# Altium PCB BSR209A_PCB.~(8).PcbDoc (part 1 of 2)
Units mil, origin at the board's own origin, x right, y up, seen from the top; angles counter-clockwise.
Board outline 3820.03 x 2030.03 mil, 4 copper layers (Top Layer, MidLayer1, MidLayer2, Bottom Layer), stack 59.4 mil thick; 68 components, 18 nets, 122 pads, 73 vias.
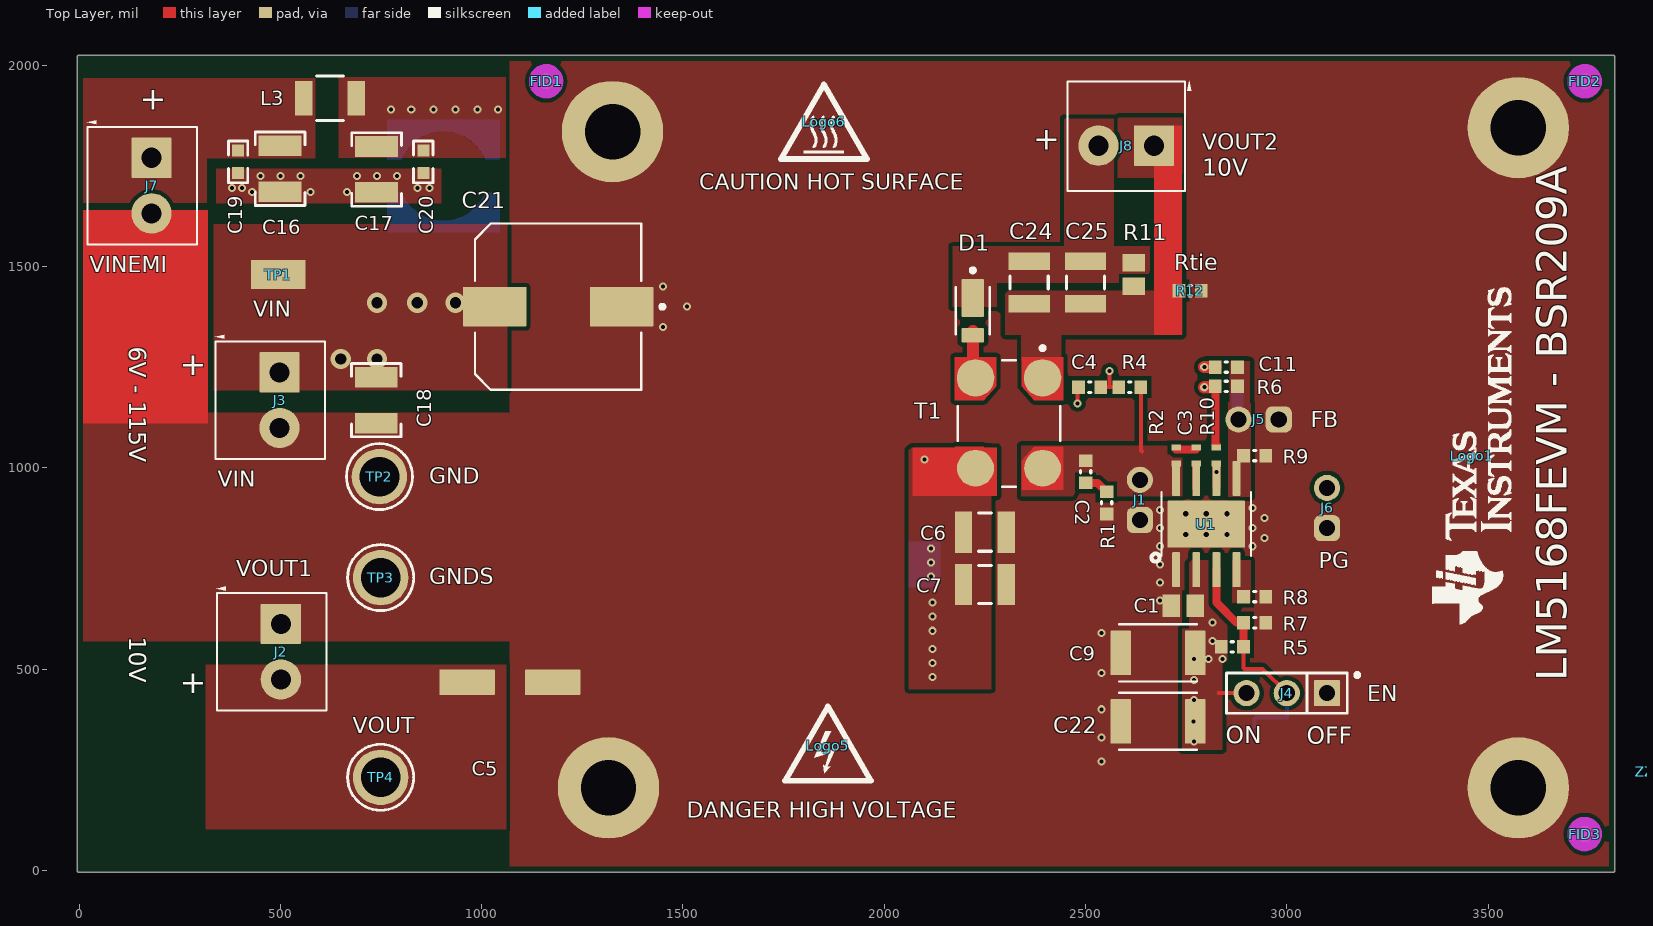
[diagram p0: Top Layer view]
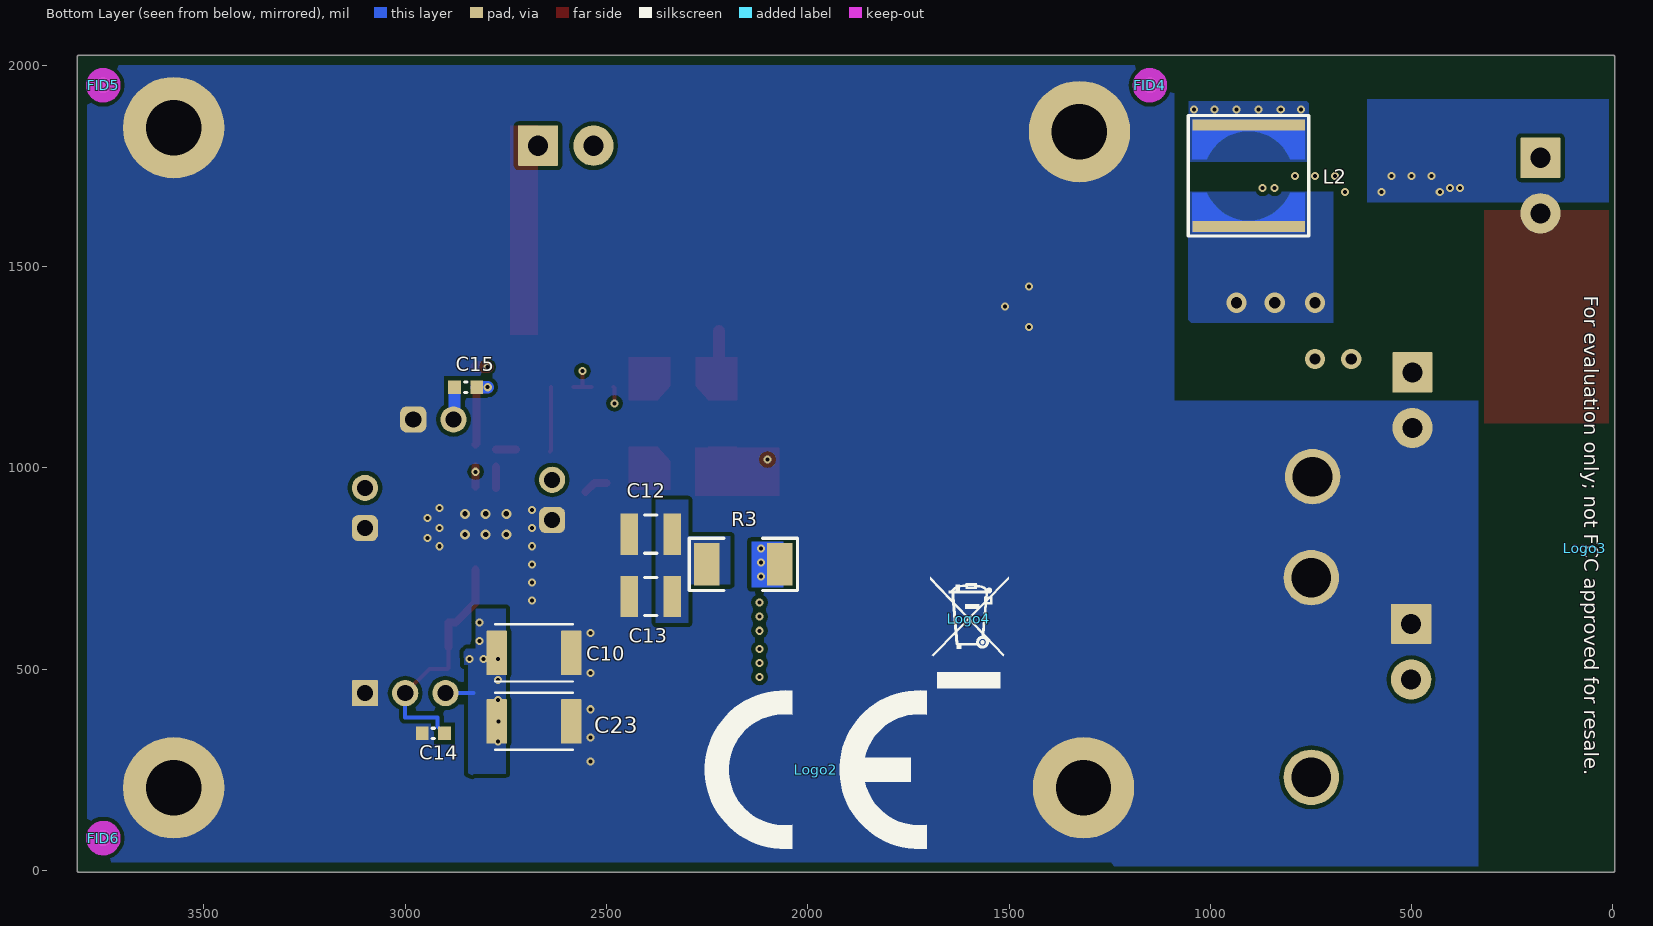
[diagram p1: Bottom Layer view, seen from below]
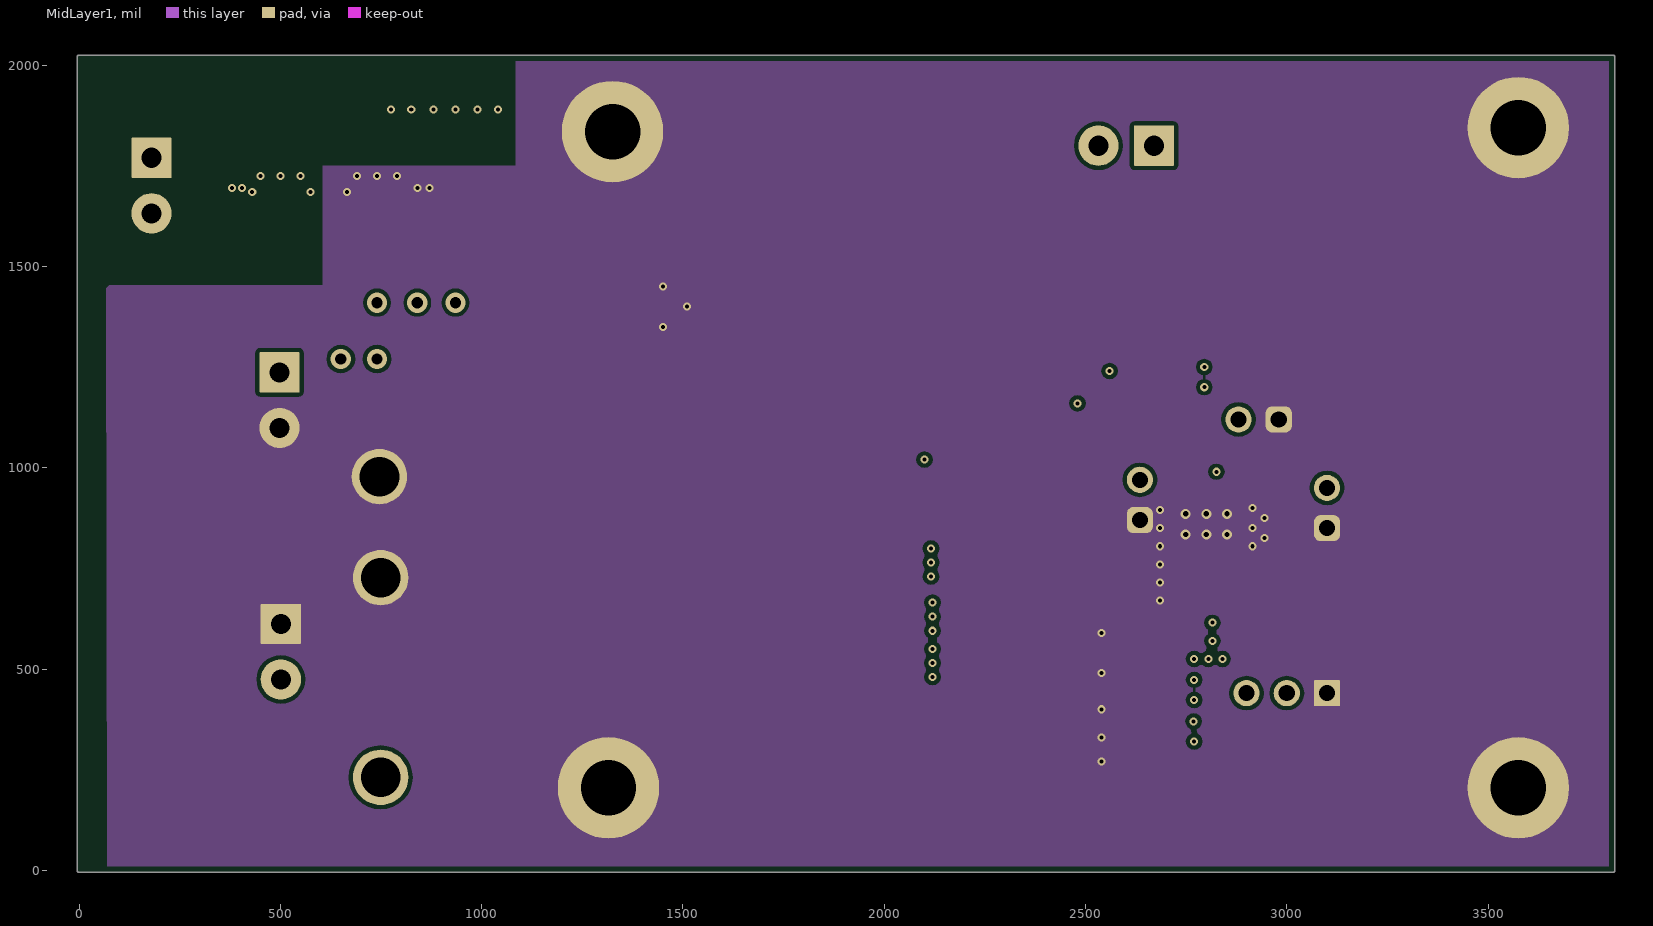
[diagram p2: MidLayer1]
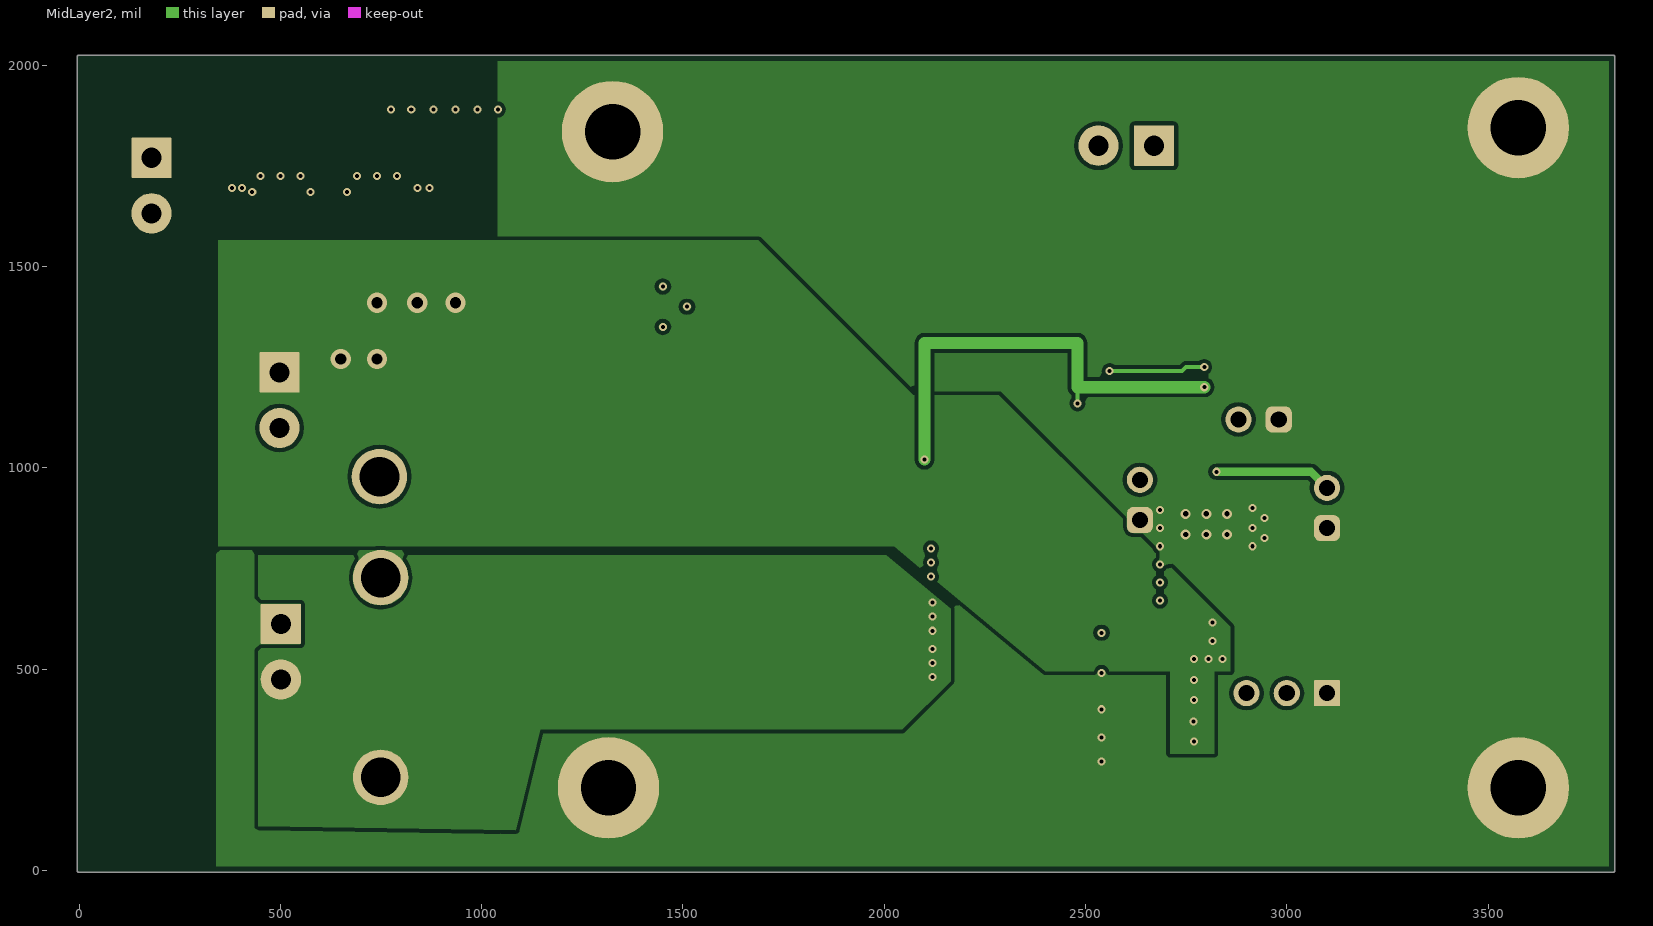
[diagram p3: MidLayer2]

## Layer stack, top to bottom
Top Solder: solder mask 0.4, Solder Resist, Dk 3.5
Top Layer: signal copper 2.8
Dielectric1: core 10, FR-4, Dk 4.8
MidLayer1: signal copper 1.4
Dielectric2: prepreg 31, FR-4, Dk 4.8
MidLayer2: signal copper 1.4
Dielectric3: core 10, FR-4, Dk 4.8
Bottom Layer: signal copper 2.8
Bottom Solder: solder mask 0.4, Solder Resist, Dk 3.5

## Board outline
0,-5.01 cw(c0,0) -5.02,0 -5.02,2020 cw(c0,2020) 0,2025.02 3810,2025.02 cw(c3810,2020) 3815.02,2020 3815.02,0 cw(c3810,0) 3810,-5.01 318,-5.01 cw(c318,0) 316.5,-4.79 cw(c315,0) 315,-5.01

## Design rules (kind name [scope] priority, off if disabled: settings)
AcuteAngle [All] p1: minimum=4.50000000000000E+0001 checktracksonly=TRUE
AssemblyTestPointUsage [All] p1: valid=2
BoardOutlineClearance BoardOutlineClearance_MountingHoles [OnCopper and InComponentClass('Mounting Holes')] p1: gap=40 ignorepadtopadclearanceinfootprint=FALSE
BoardOutlineClearance BoardOutlineClearance_Poly [OnCopper and IsPoly] p2: gap=15 ignorepadtopadclearanceinfootprint=FALSE
BoardOutlineClearance [OnCopper and Not InComponentClass('Logo') and not InComponentClass('FiducialMark') and not InRegion(1000,500,4000,800) and not InPoly] p3: gap=20 ignorepadtopadclearanceinfootprint=FALSE
Clearance Clearance_Keepouts [((IsTrack Or IsArc) And Not InPoly) And IsFree and IsKeepOut vs ((IsTrack Or IsArc) And Not InPoly) And IsFree and IsKeepOut] p1: gap=0 ignorepadtopadclearanceinfootprint=TRUE
Clearance Clearance_Poly [InPolygon] p2: gap=10 ignorepadtopadclearanceinfootprint=TRUE except(0: Arc-Hole Track-Hole SMDPad-Hole THPad-Hole Via-Hole Fill-Hole Poly-Hole Region-Hole Text-Hole)
Clearance Clearance_FiducialMark [IsKeepOut and InComponentClass('FiducialMark') vs IsPad and InComponentClass('FiducialMark')] p3: gap=0 ignorepadtopadclearanceinfootprint=TRUE
Clearance [All] p4: gap=5 ignorepadtopadclearanceinfootprint=TRUE except(0: Arc-Hole Track-Hole SMDPad-Hole THPad-Hole Via-Hole Fill-Hole Poly-Hole Region-Hole Text-Hole)
ComponentClearance ComponentClearance_MountingHoles_FiducialMarks [InComponentClass('Mounting Holes') vs InComponentClass('FiducialMark')] p1: gap=10 collisioncheckmode=3 verticalgap=10 showdistances=FALSE
ComponentClearance ComponentClearance_Shunt [InComponentClass('Header') vs InComponentClass('Shunt')] p2: gap=0 collisioncheckmode=3 verticalgap=0 showdistances=FALSE
ComponentClearance ComponentClearance_Logo [InComponentClass('Logo')] p3: gap=10 collisioncheckmode=3 verticalgap=10 showdistances=FALSE
ComponentClearance ComponentClearance_ScrewToNut [(HasFootprint('NY PMS 440 0025 PH')) vs (HasFootprint('Keystone_1902C'))] p4: gap=5 collisioncheckmode=3 verticalgap=10 showdistances=FALSE
ComponentClearance ComponentClearance_MountingHoles [InComponentClass('Mounting Holes')] p5: gap=10 collisioncheckmode=3 verticalgap=100000 showdistances=FALSE
ComponentClearance ComponentClearance_SmallPassives [HasFootprint('0201*') or HasFootprint('0402*') or HasFootprint('0508') or HasFootprint('0603*') or HasFootprint('0612') or HasFootprint('0805*') or HasFootprint('0815*') or HasFootprint('0830*') or HasFootprint('1206*') or HasFootprint('1210*') or HasFootprint('1808*') or HasFootprint('1812*') or HasFootprint('1825*') or HasFootprint('2010*') or HasFootprint('2220*') or HasFootprint('2225*') or HasFootprint('2512*') or HasFootprint('2728*') or HasFootprint('3518*') vs HasFootprint('0201*') or HasFootprint('0402*') or HasFootprint('0508') or HasFootprint('0603*') or HasFootprint('0612') or HasFootprint('0805*') or HasFootprint('0815*') or HasFootprint('0830*') or HasFootprint('1206*') or HasFootprint('1210*') or HasFootprint('1808*') or HasFootprint('1812*') or HasFootprint('1825*') or HasFootprint('2010*') or HasFootprint('2220*') or HasFootprint('2225*') or HasFootprint('2512*') or HasFootprint('2728*') or HasFootprint('3518*')] p6: gap=10 collisioncheckmode=3 verticalgap=10 showdistances=FALSE
ComponentClearance ComponentClearance_THtoSMT [IsThruComponent vs IsSMTComponent] p7: gap=10 collisioncheckmode=3 verticalgap=30 showdistances=FALSE
ComponentClearance ComponentClearance_THtoTH [IsThruComponent vs IsThruComponent] p8: gap=10 collisioncheckmode=3 verticalgap=30 showdistances=FALSE
ComponentClearance [All] p9: gap=10 collisioncheckmode=3 verticalgap=30 showdistances=FALSE
DiffPairsRouting [All] p1: maxlimit=100 minlimit=10 mostfreqgap=10 toplayer_minwidth=15 toplayer_maxwidth=15 toplayer_prefwidth=15 midlayer1_minwidth=15 midlayer1_maxwidth=15 midlayer1_prefwidth=15 midlayer2_minwidth=15 midlayer2_maxwidth=15 midlayer2_prefwidth=15 bottomlayer_minwidth=15 bottomlayer_maxwidth=15 bottomlayer_prefwidth=15 maxuncoupledlength=1000
FabricationTestPointUsage TestPointUsage [All] p1: valid=2 allowmultiple=FALSE
FabricationTestpoint Testpoint [All] p1: side=3 testpointundercomponent=TRUE minsize=40 maxsize=100 preferedsize=60 minholesize=0 maxholesize=40 preferedholesize=32 testpointgrid=1 allowsidetop=TRUE allowsidebottom=TRUE usegrid=TRUE gridtolerance=0.01
FanoutControl Fanout_LCC [IsLCC] p1: bgadir=Out bgaviamode=Centered fanoutstyle=Auto fanoutdirection=Alternating viagrid=1 // Fanout_LCC (Default Rule)
FanoutControl Fanout_BGA [IsBGA] p2: bgadir=Out bgaviamode=Centered fanoutstyle=Auto fanoutdirection=Alternating viagrid=1 // Fanout_BGA (Default Rule)
FanoutControl Fanout_Default [All] p4: bgadir=Out bgaviamode=Centered fanoutstyle=Auto fanoutdirection=Alternating viagrid=1 // Fanout_Default (Default Rule)
FanoutControl Fanout_Small [(CompPinCount < 5)] p5: bgadir=Out bgaviamode=Centered fanoutstyle=Auto fanoutdirection=OutThenIn viagrid=1 // Fanout_Small (Default Rule)
HoleSize [All] p1: absolutevalues=TRUE maxlimit=251 minlimit=7.87 maxpercent=80.000 minpercent=20.000
MinimumAnnularRing MinimumAnnularRing_ThermalPadVias [IsVia and InAnyComponent] p1: minimumring=5
MinimumAnnularRing [All] p2: minimumring=5
MinimumSolderMaskSliver MinimumSolderMaskSliver_Logo [InComponentClass('Logo') vs InComponentClass('Logo')] p1: minsoldermaskwidth=0.7
MinimumSolderMaskSliver [All] p2: minsoldermaskwidth=3.94
PlaneClearance PlaneClearance_1 [OnLayer('Top Layer')] p1: clearance=7.87
PlaneClearance [All] p2: clearance=9.84
PlaneConnect PlaneConnect_via [IsVia] p1: planeconnectstyle=Direct reliefexpansion=20 reliefentries=4 reliefconductorwidth=10 reliefairgap=10
PlaneConnect [All] p2: planeconnectstyle=Direct reliefexpansion=10 reliefentries=4 reliefconductorwidth=10 reliefairgap=10
PolygonConnect PolygonConnect_tp [(InComponent('TP*') or InComponent('J4*') or InComponent('J3*') or InComponent('X7') or InComponent('X9'))] p1: connectstyle=Direct reliefconductorwidth=10 reliefentries=4 polygonreliefangle="90 Angle" airgapwidth=10
PolygonConnect PolygonConnect_logo [InComponent('Logo1')] p2: connectstyle=Direct reliefconductorwidth=10 reliefentries=4 polygonreliefangle="90 Angle" airgapwidth=10
PolygonConnect PolygonConnect_Via [IsVia] p3: connectstyle=Direct reliefconductorwidth=10 reliefentries=4 polygonreliefangle="90 Angle" airgapwidth=10
PolygonConnect PolygonConnect_1 [HasFootprint('HARWIN_S1911-46R')] p4: connectstyle=Direct reliefconductorwidth=39.37 reliefentries=4 polygonreliefangle="90 Angle" airgapwidth=7.87
PolygonConnect PolygonConnect_poly [IsPoly] p5: connectstyle=Direct reliefconductorwidth=30 reliefentries=4 polygonreliefangle="90 Angle" airgapwidth=8
PolygonConnect [All] p6: connectstyle=Relief reliefconductorwidth=30 reliefentries=4 polygonreliefangle="90 Angle" airgapwidth=8
RoutingVias ThermalPadVias [IsVia and InAnyComponent] p1: holewidth=7.87 width=19.68 viastyle="Through Hole" minholewidth=7.87 minwidth=19.68 maxholewidth=12.99 maxwidth=25
RoutingVias [All] p2: holewidth=16 width=34 viastyle="Through Hole" minholewidth=7 minwidth=20 maxholewidth=40 maxwidth=65
SilkToSilkClearance SilkToSilkClearance_Pb-FreeLogo [(HasFootprint('Pb-Free_Overlay_Medium') OR HasFootprint('Pb-Free_Overlay_Small')) vs (HasFootprint('Pb-Free_Overlay_Medium') OR HasFootprint('Pb-Free_Overlay_Small'))] p1: silktosilkclearance=0
SilkToSilkClearance [All] p2: silktosilkclearance=3
SilkToSolderMaskClearance SilkToComponentPadClearance [(IsPad or IsFill or IsRegion) and InAnycomponent] p1: minsilkscreentomaskgap=5 clearancetoexposedcopper=TRUE
SilkToSolderMaskClearance "Silk to Solder Mask Opening" [All] p2: minsilkscreentomaskgap=4 clearancetoexposedcopper=FALSE
SolderMaskExpansion [All] p1: expansion=1.97
Width [All] p1: maxlimit=100 minlimit=6 preferedwidth=10 checkconnectedcopper=TRUE
15 further rules are at their usual default settings.

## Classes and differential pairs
component class FiducialMark: FID1 FID2 FID3 FID4 FID5 FID6
component class Header: J1 J4 J5 J6
component class Logo: Logo1
component class BSR209A_Hardware: !PCB FID1 FID2 FID3 FID4 FID5 FID6 Logo1 Logo2 Logo3 Logo4 Logo5 Logo6 ZZ2 ZZ3 ZZ4
component class AssemblyNote: ZZ2 ZZ3 ZZ4
component class BSR209A_sch: 30 500kHz C1 C2 C3 C4 C5 C6 C7 C9 C10 C11 C12 C13 C14 C15 C16 C17 C18 C19 C20 C21 C22 C23 C24 C25 CIN1 COUT2 COUT3 D1 gnd J1 J2 J3 J4 J5 J6 J7 J8 L2 L3 R1 R2 R3 R4 R5 R6 R7 R8 R9 R10 R11 R12 T1 TP1 TP2 TP3 TP4 TPCLK180 U1 vin Vout

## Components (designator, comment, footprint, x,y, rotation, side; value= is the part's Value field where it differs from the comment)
C1 "C2012X7T2E104K125AA" 0805L 2742.79,657.21 r180 top value=0.1uF
C2 "GRM188R72D102KW07D" 0603L 2500,990 r90 top value=1000pF
C3 "GCM155R71H222KA37D" 0402S 2775,1030 r270 top value=2200pF
C4 "CR" 0603L 2510,1200 r0 top value=3300pF
C5 "UWT1E101MCL1GS" UWT_630x770 1070,467 r0 top value=100uF
C6 "GRT32ER61E226KE13L" 1210_270L 2250,840 r0 top value=22uF
C7 "GRT32ER61E226KE13L" 1210_270L 2250,710 r0 top value=22uF
C9 "CGA8P3X7T2E105K250KE" FP-CGA8P3X7T2E105K250KE_1812-MFG 2680,540 r0 top value=1µF
C10 "CGA8P3X7T2E105K250KE" FP-CGA8P3X7T2E105K250KE_1812-MFG 2680,540 r0 bottom value=1µF
C11 "C0603C560J5GACTU" 0603L 2850,1250 r0 top value=56pF
C12 "COUT3" 1210_270L 2390,835 r0 bottom value=22uF
C13 "COUT4" 1210_270L 2390,680 r0 bottom value=22uF
C14 "CEN" 0603L 2930,340 r0 bottom value=0.01uF
C15 "CFF" 0603L 2850,1200 r0 bottom value=1000pF
C16 "CGA6M3X7S2A475K200AB" 1210_220 499,1743 r270 top value=4.7uF
C17 "CGA6M3X7S2A475K200AB" 1210_220 739,1741 r270 top value=4.7uF
C18 "CGA6M3X7S2A475K200AB" 1210_220 738,1168 r270 top value=4.7uF
C19 "HMK107B7104KAHT" 0603_HV 395,1760 r270 top value=0.1uF
C20 "HMK107B7104KAHT" 0603_HV 855,1760 r270 top value=0.1uF
C21 "ULT2C330MNL1GS" FP-ULT2C330MNL1GS_RADIAL-MFG 1190,1400 r180 top value=33µF
C22 "CGA8P3X7T2E105K250KE" FP-CGA8P3X7T2E105K250KE_1812-MFG 2680,370 r0 top value=1µF
C23 "CGA8P3X7T2E105K250KE" FP-CGA8P3X7T2E105K250KE_1812-MFG 2680,370 r0 bottom value=1µF
C24 "GRT32ER61E226KE13L" 1210_270L 2360,1460 r270 top value=22uF
C25 "GRT32ER61E226KE13L" 1210_270L 2500,1460 r270 top value=22uF
D1 "SS1H20LS RVG" "FP-SS1H20LS RVG_SOD123HE-MFG" 2220,1390 r270 top
FID1 "Fiducial" Fiducial10-20 1160,1960 r90 top
FID2 "Fiducial" Fiducial10-20 3740,1960 r90 top
FID3 "Fiducial" Fiducial10-20 3740,90 r90 top
FID4 "Fiducial" Fiducial10-20 1150,1950 r90 bottom
FID5 "Fiducial" Fiducial10-20 3750,1950 r90 bottom
FID6 "Fiducial" Fiducial10-20 3750,80 r90 bottom
J1 "SW" TSW-102-07-G-S 2635,920 r90 top
J2 "VOUT1" TERM_BLK_ED555-2DS 501,612 r270 top
J3 "VIN" TERM_BLK_ED555-2DS 498,1237 r270 top
J4 "EN" Samtec_HTSW-103-07-G-S 3000,440 r180 top
J5 "FB" TSW-102-07-G-S 2930,1120 r180 top
J6 "PG" TSW-102-07-G-S 3100,900 r90 top
J7 "VINEMI" TERM_BLK_ED555-2DS 180,1770 r270 top
J8 "VOUT2" TERM_BLK_ED555-2DS 2670,1800 r180 top
L2 "MSS7341T-153MLB" MSS7341 905,1725 r270 bottom value=15uH
L3 "FBMH3225HM202NT" 1210_280 623,1918 r0 top value="2000 ohm"
Logo1 "Texas Instruments" TI_Stacked_Overlay_Small 3460,1030 r90 top
Logo2 "CE Mark" CE_Mark_10mm 1980,250 r180 bottom
Logo3 "FCC disclaimer" FCC_disclaimer 70,800 r270 bottom
Logo4 "WEEE logo" WEEE_Minimum 1600,625 r180 bottom
Logo5 "DANGER HIGH VOLTAGE" IEC_HighVoltage_Small 1860,310 r0 top
Logo6 "CAUTION HOT SURFACE" IEC_HotSurface_Small 1850,1860 r0 top
R1 "CRCW06031R00JNEA" 0603L 2552.2,912.8 r90 top value=1.0
R2 "RBST" 0402S 2725,1030 r270 top value=0
R3 "DNP" 2010 2160,760 r180 bottom value=0.2
R4 "RC0603FR-07118KL" 0603L 2610,1200 r180 top value=118k
R5 "RC0603FR-071ML" 0603L 2865,555 r180 top value=1.00Meg
R6 "RC0603FR-07453KL" 0603L 2850,1202 r180 top value=453k
R7 "RC0603FR-07332KL" 0603L 2920,615 r180 top value=332k
R8 "RC0603FR-0733K2L" 0603L 2920,680 r180 top value=33.2k
R9 "RC0603FR-0761K9L" 0603L 2920,1030 r180 top value=61.9k
R10 "ERJ-2RKF1003X" 0402S 2825,1030 r90 top value=100k
R11 "CRCW08051K00FKEA" 0805L 2620,1480 r90 top value=1.00k
R12 "Rtie" 0603L 2760,1440 r0 top value=0
T1 "LPD8035V-333MRC" FP-LPD8035V-333MRC_SMD4-MFG 2310,1110 r270 top
TP1 "VIN" Harwin_S1751-46 495,1480 r0 top
TP2 "GND" Keystone1598-2 746,978 r90 top value=Triple
TP3 "GNDS" Keystone1598-2 749,727 r90 top value=Triple
TP4 "VOUT" Keystone1598-2 749,231 r90 top value=Triple
U1 "LM5168FQDDARQ1" DDA0008E-MFG 2800,860 r90 top
ZZ2 "These assemblies are ESD sensitive, ESD precautions shall be observed." AssemblyNote 4250,245 r90 top
ZZ3 "These assemblies must be clean and free from flux and all contaminants. Use of no clean flux is not acceptable." AssemblyNote 4070,245 r90 top
ZZ4 "These assemblies must comply with workmanship standards IPC-A-610 Class 2, unless otherwise specified." AssemblyNote 3900,245 r90 top

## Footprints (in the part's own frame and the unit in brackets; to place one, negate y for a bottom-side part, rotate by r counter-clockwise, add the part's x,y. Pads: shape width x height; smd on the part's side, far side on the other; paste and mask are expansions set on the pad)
0402S [mil] "Based on C0402S footprint from PADS legacy"
  rect 15x24 smd: 1(-20,0) 2(20,0)
  body extent -22,-12 22,12, height 24
0603_HV [mil] "Ernesto recommended land pattern.  26 mil between pads."
  rect 30x30 smd: 1(-28,0) 2(28,0)
  silkscreen extent -52,-24 52,24, body extent -34,-19 34,19, height 39
0603L [mm] "0603 from SM-752 data"
  rect 0.8x0.85 smd: 1(-0.7,0) 2(0.7,0)
  silkscreen extent -0.07,-0.33 0.07,0.33, body extent -0.87,-0.47 0.87,0.47, height 1
0805L [mm] "0805 from SM-752 data"
  rect 1.1x1.4 smd: 1(-0.75,0) 2(0.75,0)
  body extent -1.1,-0.72 1.1,0.72, height 1.45
1210_220 [mm] "1210"
  rect 1.3x2.7 smd: 1(-1.45,0) 2(1.45,0)
  silkscreen extent -2.32,-1.57 2.32,1.57, body extent -1.7,-1.35 1.7,1.35, height 2.2
1210_270L [mm] "1210"
  rect 1.1x2.6 smd: 1(-1.35,0) 2(1.35,0)
  silkscreen extent -0.4,-1.2 0.4,1.2, body extent -1.7,-1.35 1.7,1.35, height 2.7
1210_280 [mm] "SMD, 2-Leads, Body 3.6x2.8mm, Height 2.8mm"
  rect 1.1x2.2 smd: 1(-1.65,0) 2(1.65,0)
  silkscreen extent -0.84,-1.4 0.84,1.4, body extent -1.8,-1.4 1.8,1.4, height 2.8
2010 [mm] "Chip Capacitor, Body 5.08x2.54mm, IPC Medium Density"
  rect 1.6x2.7 smd: 1(-2.3,0) 2(2.3,0)
  silkscreen extent -3.42,-1.65 3.42,1.65, body extent -2.73,-1.45 2.73,1.45, height 1.66
AssemblyNote [mil] "Assembly Note"
CE_Mark_10mm [mil] "Double the minimum text height for CE Mark"
  silkscreen extent -275,-197 276,197
DDA0008E-MFG [mm]
  rrect20% 2.2x0.5 smd paste-1000 mask+0: 1(-2.875,1.905) 2(-2.875,0.635) 3(-2.875,-0.635) 4(-2.875,-1.905) 5(2.875,-1.905) 6(2.875,-0.635) 7(2.875,0.635) 8(2.875,1.905)
  rrect3% 2.95x4.9 smd paste-1000 mask-1000: 9(0,0)
  silkscreen extent -2,-2.83 2,2.83, body extent -4.08,-2.68 4.08,2.68, height 0.25
FCC_disclaimer [mil]
Fiducial10-20 [mm]
  round 1 smd mask+0.5: 1(0,0)
  Top Layer keep-out circle w1.178: c0,0 r0.5
FP-CGA8P3X7T2E105K250KE_1812-MFG [mm]
  rrect8% 1.3x2.8 smd paste+0 mask+0: 1(-2.35,0) 2(2.35,0)
  silkscreen extent -2.45,-1.8 2.45,1.8, body extent -3.1,-1.9 3.1,1.9, height 0.25
FP-LPD8035V-333MRC_SMD4-MFG [mm]
  round 2.367 smd paste+0 mask+0: 1(-2.875,2.115) 2(-2.875,-2.115)
  round 2.325 smd paste+0 mask+0: 3(2.822,-2.115) 4(2.822,2.115)
  Top Layer region: 4.19,-3.43 1.455,-3.43 1.455,-1.6 2.36,-0.8 4.19,-0.8
  Top Layer region: 4.19,3.43 1.455,3.43 1.455,1.6 2.36,0.8 4.19,0.8
  Top Layer region: -4.19,-3.43 -1.455,-3.43 -1.455,-1.6 -2.36,-0.8 -4.19,-0.8
  Top Layer region: -4.19,3.43 -1.455,3.43 -1.455,1.6 -2.36,0.8 -4.19,0.8
  silkscreen extent -4.87,-3.24 4,3.24, body extent -4.29,-3.53 4.29,3.53, height 0.25
"FP-SS1H20LS RVG_SOD123HE-MFG" [mm]
  rrect7% 2.4x1.4 smd paste+0 mask+0: 1(-0.8,0)
  rrect11% 0.9x1.4 smd paste+0 mask+0: 2(1.55,0)
  silkscreen extent -2.67,-1.07 1.5,1.07, body extent -2.1,-1.07 2.1,1.07, height 0.25
FP-ULT2C330MNL1GS_RADIAL-MFG [mm]
  rrect4% 4x2.5 smd paste+0 mask+0: 1(-4,0) 2(4,0)
  silkscreen extent -6.7,-5.25 5.25,5.25, body extent -6.25,-5.5 6.25,5.5, height 0.25
Harwin_S1751-46 [mm] "Test Point, Body 3.25x1.65mm"
  rect 3.45x1.85 smd: 1(0,0)
  body extent -1.62,-0.82 1.63,0.82, height 2.05
IEC_HighVoltage_Small [mil]
  silkscreen extent -107,-88 107,97
IEC_HotSurface_Small [mil]
  silkscreen extent -107,-93 107,92
Keystone1598-2 [mm] "Triple Turret"
  round 3.5 hole 2.5: 1(0,0)
  silkscreen extent -2.08,-2.08 2.08,2.08, body extent -1.6,-1.6 1.59,1.6, height 7.72
MSS7341 [mm] "Coilcraft recommended land pattern Document 383-2 1/3/11"
  rect 0.7x7.1 smd: 1(-3.2,0) 2(3.2,0)
  Top Layer region: 1.05,3.55 3.55,3.55 3.55,-3.55 1.05,-3.55 1.05,-2.623 2.135,-1.85 2.745,-0.666 2.745,0.666 2.135,1.85 1.05,2.623 1.05,2.623
  Top Layer region: -1.05,3.55 -3.55,3.55 -3.55,-3.55 -1.05,-3.55 -1.05,-2.623 -2.135,-1.85 -2.745,-0.666 -2.745,0.666 -2.135,1.85 -1.05,2.623 -1.05,2.623
  silkscreen extent -3.8,-3.8 3.8,3.8, body extent -3.78,-3.78 3.78,3.78, height 4.12
Samtec_HTSW-103-07-G-S [mm] "Samtec 100mil, 1x3, 230 mil above insulator"
  rrect6% 1.65x1.65 hole 1.016: 1(-2.54,0)
  round 1.65 hole 1.016: 2(0,0) 3(2.54,0)
  silkscreen extent -4.57,-1.27 3.81,1.27, body extent -3.81,-1.27 3.81,1.27, height 8.38
TERM_BLK_ED555-2DS [mil]
  rrect4% 100x100 hole 50: 1(0,0)
  round 100 hole 50: 2(138,0)
  silkscreen extent -93,-161 215,113, body extent -69,-150 207,106, height 323
TI_Stacked_Overlay_Small [mil]
  silkscreen extent -418,-98 418,98
TSW-102-07-G-S [mm] "Samtec 100mil, 1x2, 230 mil above insulator"
  rrect50% 1.65x1.65 hole 1.016: 1(-1.27,0)
  round 1.65 hole 1.016: 2(1.27,0)
  body extent -2.54,-1.27 2.54,1.27, height 8.38
UWT_630x770 [mm] "SMD, 2-Leads, Dia 6.3mm"
  rrect6% 3.5x1.6 smd: 1(-2.7,0) 2(2.7,0)
  body extent -3.5,-3.3 3.5,3.3, height 8
WEEE_Minimum [mil] "WEEElie bin"
  silkscreen extent -95,-172 99,104

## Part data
C1: library part CMP-0007897-1, "CAP, CERM, 0.1 uF, 250 V, +/- 10%, X7T, 0805", Cap_Case=0805, Manufacturer=TDK, Supplier Part Number 1=445-7749-1-ND, TempCo=X7T, Tolerance_%=10%, Value1=Unknown, Value2=250V, ValueDisplayed=0.1uF
C2: library part CMP-0081318-1, "CAP, CERM, 1000 pF, 200 V,+/- 10%, X7R, 0603", Cap_Case=0603, Manufacturer=MuRata, Supplier Part Number 1=490-14641-1-ND, TempCo=X7R, Tolerance_%=10%, Value2=200V, ValueDisplayed=1000pF
C3: library part CMP-0006357-2, "CAP, CERM, 2200 pF, 50 V, +/- 10%, X7R, AEC-Q200 Grade 1, 0402", Cap_Case=0402, Manufacturer=MuRata, Supplier Part Number 1=490-4914-1-ND, TempCo=X7R, Tolerance_%=10%, Value1=Unknown, Value2=50V, ValueDisplayed=2200pF
C4: library part CMP-0007087-4, "CAP, CERM, 3300 pF, 100 V, +/- 10%, X7R, AEC-Q200 Grade 1, 0603", Cap_Case=0603, Manufacturer=TDK, PartNumber=CGA3E2X7R2A332K080AA, Supplier Part Number 1=445-5809-1-ND, TempCo=X7R, Tolerance_%=10%, Value1="0.662155 ohm", Value2=100V, ValueDisplayed=3300pF
C5: library part CMP-0081462-1, "CAP, AL, 100 µF, 25 V, +/- 20%, SMD", Cap_Case=6.3x7.7mm, Manufacturer=Nichicon, Supplier Part Number 1=493-2190-1-ND, Tolerance_%=20%, Value2=25V, ValueDisplayed=100µF
C6 C7 C24 C25: library part CMP-0084059-1, "CAP, CERM, 22 µF, 25 V,+/- 10%, X5R, AEC-Q200 Grade 3, 1210", Cap_Case=1210, Manufacturer=MuRata, TempCo=X5R, Tolerance_%=10%, Value2=25V, ValueDisplayed=22µF
C9 C10 C22 C23: library part CMP-0091301-1, "Cap Ceramic 1uF 250V X7T 10% Pad SMD 1812 +125°C Automotive T/R", Manufacturer=TDK, Operating Temperature Range="-55°C to +125°C", TempCo=+22/-33%, Temperature Characteristic=X7T, Tolerance_%=0.1%, ValueDisplayed=1uF
C11: library part CMP-0006952-4, "CAP, CERM, 56 pF, 50 V, +/- 5%, C0G/NP0, 0603", Cap_Case=0603, Manufacturer=Kemet, Supplier Part Number 1=399-1057-1-ND, TempCo=C0G/NP0, Tolerance_%=5%, Value1=Unknown, Value2=50V, ValueDisplayed=56pF
C12 C13: library part CMP-0009255-2, "CAP, CERM, 22 uF, 25 V, +/- 10%, X7R, AEC-Q200 Grade 1, 1210", Cap_Case=1210, Manufacturer="Taiyo Yuden", PartNumber=TMK325B7226KMHT, Supplier Part Number 1=587-4337-1-ND, TempCo=X7R, Tolerance_%=10%, Value1=Unknown, Value2=25V, ValueDisplayed=22uF
C14: library part CMP-0080063-1, "CAP, CERM, 0.01 µF, 100 V,+/- 10%, X8R, AEC-Q200 Grade 0, 0603", Cap_Case=0603, Manufacturer=TDK, PartNumber=CGA3E2X8R2A103K080AD, Supplier Part Number 1=445-8825-1-ND, TempCo=X8R, Tolerance_%=10%, Value2=100V, ValueDisplayed=0.01µF
C15: library part CMP-0006844-4, "CAP, CERM, 1000 pF, 50 V, +/- 5%, X7R, AEC-Q200 Grade 1, 0603", Cap_Case=0603, Manufacturer=Kemet, PartNumber=C0603C102J5RACAUTO, Supplier Part Number 1=399-12989-1-ND, TempCo=X7R, Tolerance_%=5%, Value1=Unknown, Value2=50V, ValueDisplayed=1000pF
C16 C17 C18: library part CMP-0009150-2, "CAP, CERM, 4.7 uF, 100 V, +/- 10%, X7S, AEC-Q200 Grade 1, 1210", Cap_Case=1210_220, Manufacturer=TDK, Supplier Part Number 1=445-7005-1-ND, TempCo=X7S, Tolerance_%=10%, Value1="0.004236 ohm", Value2=100V, ValueDisplayed=4.7uF
C19 C20: library part CMP-0081011-1, "CAP, CERM, 0.1 µF, 100 V,+/- 10%, X7R, AEC-Q200 Grade 1, 0603", Cap_Case=0603, Manufacturer="Taiyo Yuden", Supplier Part Number 1=587-6009-1-ND, TempCo=X7R, Tolerance_%=10%, Value2=100V, ValueDisplayed=0.1µF
C21: library part CMP-0091226-1, "Aluminum Electrolytic Capacitors Radial 33uF 20% 160V, Can - SMD - 2000 Hrs @ 125°C", Digikey Part Number=493-6719-1-ND, Leakage Current=311.2uA, Manufacturer=Nichicon, Mouser Part Number=647-ULT2C330MNL1GS, Operating Temperature Range="-40°C to +125°C", Tolerance_%=20%, ValueDisplayed=33uF
D1: library part CMP-0093179-1, "Rectifier Diode Schottky 200V 1A 2-Pin SOD-123HE T/R", Digikey Part Number=SS1H20LSRVGCT-ND, Forward Current=1A, Manufacturer="Taiwan Semiconductor", Max Surge Forward Current=30A, Mouser Part Number=821-SS1H20LSRVG, Operating Temperature Range="-55°C to +150°C", Peak Reverse Current=1uA
FID1 FID2 FID3 FID4 FID5 FID6: library part CMP-0077181-1, "Fiducial mark.  There is nothing to buy or mount.", Manufacturer=N/A
J1 J5 J6: library part CMP-0075405-2, "Header, 100mil, 2x1, Gold, TH", Color=Black, Current_A=6.3A, Manufacturer=Samtec, PartNumber=TSW-102-07-G-S, Supplier Part Number 1=SAM1029-02-ND, Voltage_V=550V
J2 J3 J7 J8: library part CMP-0074913-1, "Terminal Block, 3.5mm Pitch, 2x1, TH", Color=Grey, Current_A=6A, Manufacturer="On-Shore Technology", PartNumber=ED555/2DS, Supplier Part Number 1=ED1514-ND, Voltage_V=150V
J4: library part CMP-0075484-1, "Header, 100mil, 3x1, Gold, TH", Manufacturer=Samtec, PartNumber=HTSW-103-07-G-S, Supplier Part Number 1=HTSW-103-07-G-S-ND
L2: library part CMP-0061601-2, "Inductor, Shielded Drum Core, Ferrite, 15 uH, 1.8 A, 0.05 ohm, AEC-Q200 Grade 1, SMD", Manufacturer=Coilcraft, Value1="0.05 ohm", Value2=1.8A, ValueDisplayed=15uH
L3: library part CMP-0003373-1, "Ferrite Bead, 2000 ohm @ 100 MHz, 1.2 A, 1210", Manufacturer="Taiyo Yuden", Supplier Part Number 1=587-1754-1-ND, Value1="0.13 ohm", Value2=1.2A, ValueDisplayed="2000 ohm"
Logo1: library part CMP-0074838-1, "Texas Instrument Corporate Signature"
Logo2: library part CMP-0074844-1
Logo3: library part CMP-0074847-1, "FCC_disclaimer"
Logo4: library part CMP-0074769-1
Logo5: library part IEC_HighVoltage, "IEC 61010-1 High Voltage Warning"
Logo6: library part IEC_HotSurface, "IEC 61010-1 Hot Surface Warning"
R1: library part CMP-0025743-4, "RES, 1.0, 5%, 0.1 W, AEC-Q200 Grade 0, 0603", Manufacturer=Vishay-Dale, Power_W=100mW, Supplier Part Number 1=541-1.0GCT-ND, TempCo="200 ppm/C", Tolerance_%=5%, Value2=0.1W, Value_Code=1R00, ValueDisplayed=1.0
R2: library part CMP-0026822-3, "RES, 0, 5%, 0.063 W, AEC-Q200 Grade 0, 0402", Manufacturer=Vishay-Dale, PartNumber=CRCW04020000Z0ED, Power_W=63mW, Supplier Part Number 1=541-0.0JCT-ND, TempCo="200 ppm/C", Tolerance_%=5%, Value2=0.063W, Value_Code=0000, ValueDisplayed=0
R3: library part CMP-0016525-2, "RES, 0.2, 1%, 1 W, 2010", Manufacturer="Stackpole Electronics Inc", PartNumber=CSRN2010FKR200, Power_W=1W, Supplier Part Number 1=CSRN2010FKR200CT-ND, TempCo="250 ppm/C", Tolerance_%=1%, Value_Code=R200, ValueDisplayed=0.2
R4: library part CMP-0022758-4, "RES, 118 k, 1%, 0.1 W, 0603", Manufacturer=Yageo, Power_W=100mW, Supplier Part Number 1=311-118KHRCT-ND, TempCo="100 ppm/C", Tolerance_%=1%, Value2=0.1W, Value_Code=118k
R5: library part CMP-0022899-4, "RES, 1.00 M, 1%, 0.1 W, 0603", Manufacturer=Yageo, Power_W=100mW, Supplier Part Number 1=311-1.00MHRCT-ND, TempCo="100 ppm/C", Tolerance_%=1%, Value2=0.1W, Value_Code=1M00, ValueDisplayed=1.00M
R6: library part CMP-0023120-4, "RES, 453 k, 1%, 0.1 W, 0603", Manufacturer=Yageo, Power_W=100mW, Supplier Part Number 1=311-453KHRCT-ND, TempCo="100 ppm/C", Tolerance_%=1%, Value2=0.1W, Value_Code=453k
R7: library part CMP-0023034-4, "RES, 332 k, 1%, 0.1 W, 0603", Manufacturer=Yageo, Power_W=100mW, Supplier Part Number 1=311-332KHRCT-ND, TempCo="100 ppm/C", Tolerance_%=1%, Value2=0.1W, Value_Code=332k
R8: library part CMP-0023036-5, "RES, 33.2 k, 1%, 0.1 W, 0603", Manufacturer=Yageo, Power_W=100mW, Supplier Part Number 1=311-33.2KHRCT-ND, TempCo="100 ppm/C", Tolerance_%=1%, Value2=0.1W, Value_Code=33k2, ValueDisplayed=33.2k
R9: library part CMP-0023216-5, "RES, 61.9 k, 1%, 0.1 W, 0603", Manufacturer=Yageo, Power_W=100mW, Supplier Part Number 1=311-61.9KHRCT-ND, TempCo="100 ppm/C", Tolerance_%=1%, Value2=0.1W, Value_Code=61k9, ValueDisplayed=61.9k
R10: library part CMP-0026659-1, "RES, 100 k, 1%, 0.1 W, 0402", Manufacturer=Panasonic, Power_W=100mW, TempCo="100 ppm/C", Tolerance_%=1%, Value2=0.1W, Value_Code=100k
R11: library part CMP-0020951-3, "RES, 1.00 k, 1%, 0.125 W, AEC-Q200 Grade 0, 0805", Manufacturer=Vishay-Dale, Power_W=125mW, Supplier Part Number 1=541-1.00KCCT-ND, TempCo="100 ppm/C", Tolerance_%=1%, Value2=0.125W, Value_Code=1k00, ValueDisplayed=1.00k
R12: library part CMP-0025697-4, "RES, 0, 5%, 0.1 W, AEC-Q200 Grade 0, 0603", Manufacturer=Vishay-Dale, PartNumber=CRCW06030000Z0EA, Power_W=100mW, Supplier Part Number 1=541-0.0GCT-ND, TempCo="200 ppm/C", Tolerance_%=5%, Value2=0.1W, Value_Code=0000, ValueDisplayed=0
T1: library part CMP-0091289-1, "Power inductor, coupled, shielded, 20% tol, RoHS, halogen-free", Manufacturer=Coilcraft, Operating Temperature Range="to +125°C", Voltage_Isolation_Vrms=1500Vrms
TP1: library part CMP-0075188-1, "Test Lead clips and hooks, SMT", Current_A=2A, Manufacturer=Harwin, PartNumber=S1751-46, Supplier Part Number 1=S1751-46-ND
TP2 TP3 TP4: library part 1598-2, "Terminal, Turret, TH, Triple", Manufacturer=Keystone, Supplier Part Number 1=1598-2K-ND
U1: library part CMP-0092717-1, "0.3-A, 120-V, Step-Down Converter with Fly-buck Capability, HSOIC8", Manufacturer="Texas Instruments", Max Supply Voltage=115V, Min Supply Voltage=6V, Nominal Supply Current=10-420uA, Operating Temperature Range="-40°C to +150°C", Switching Frequency=1MHz
ZZ2: library part CMP-0077236-1
ZZ3: library part CMP-0077237-1
ZZ4: library part CMP-0077238-1

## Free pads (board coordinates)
  round 251.97 hole 137.8: 1(1315,205) 1(1325,1835) 1(3575,205) 1(3575,1845)

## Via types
v1: diameter 20, hole 10, Top Layer to Bottom Layer, tented both sides, 62 vias
v2: diameter 24.8, hole 12.99, Top Layer to Bottom Layer, 6 vias
v3: diameter 50, hole 28, Top Layer to Bottom Layer, tented both sides, 5 vias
